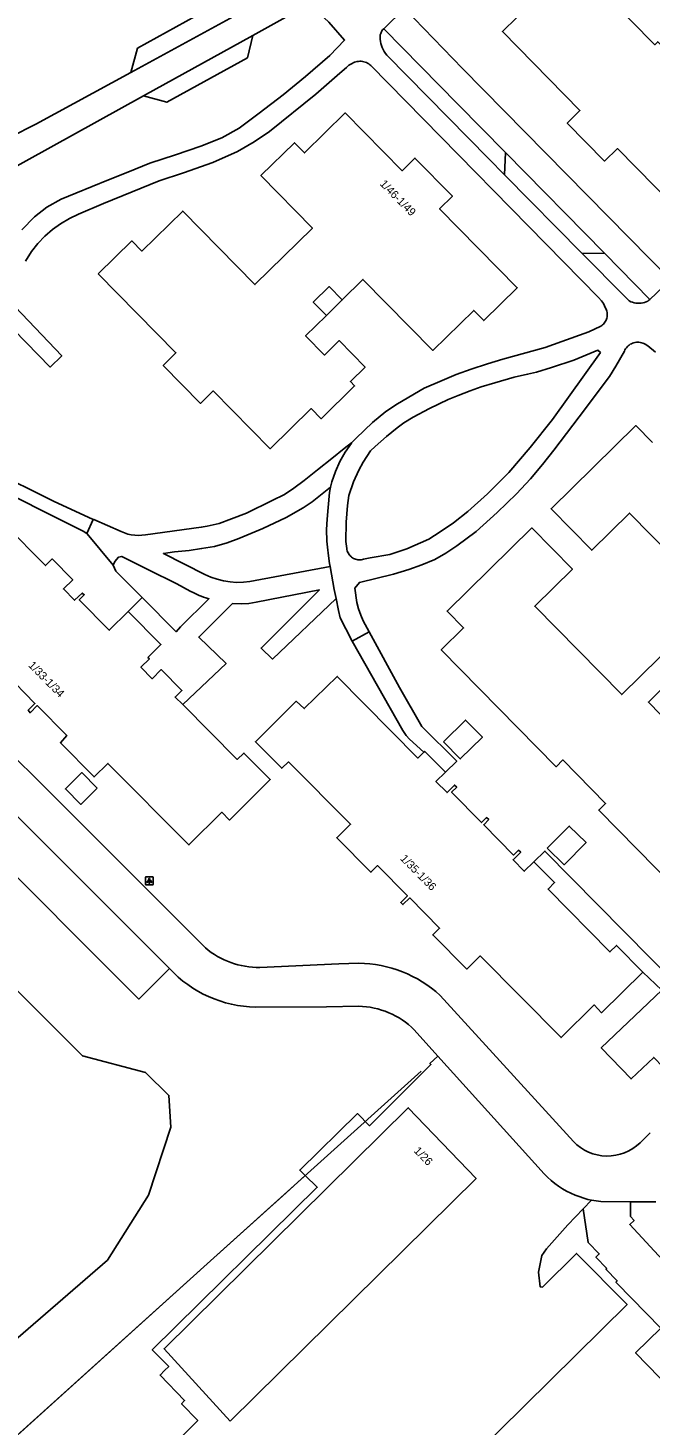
# Model space of a CAD drawing. Extents: x 162791 to 163827, y 385795 to 386523.
# Drawn here: x 162911.4 to 162989.1, y 385940.4 to 386115 of the extents above; entities that cross this region are included whole.
import ezdxf

# ---------------------------------------------------------------- set-up
doc = ezdxf.new("R2010")
doc.units = 0
for name, color, linetype in [('IMGEO_Grasland_overig', 7, 'Continuous'), ('IMGEO_Groenvoorziening', 7, 'Continuous'), ('IMGEO_Hek', 7, 'Continuous'), ('IMGEO_Lichtpunt', 7, 'Continuous'), ('IMGEO_Loofbos', 7, 'Continuous'), ('IMGEO_Pand', 7, 'Continuous'), ('IMGEO_Pand_nummerreeks', 7, 'Continuous'), ('IMGEO_Pand_overbouw', 7, 'Continuous'), ('IMGEO_Parkeervlak_halfverhard', 7, 'Continuous'), ('IMGEO_Parkeervlak_open', 7, 'Continuous'), ('IMGEO_Terreindeel_open', 7, 'Continuous'), ('IMGEO_Voetpad_open', 7, 'Continuous'), ('IMGEO_Woonerf_gesloten', 7, 'Continuous'), ('IMGEO_Woonerf_open', 7, 'Continuous')]:
    doc.layers.add(name, color=color, linetype=linetype)

msp = doc.modelspace()

# ---------------------------------------------------------------- linework, layer by layer
at = {"layer": 'IMGEO_Grasland_overig'}
for points in [[(162946.01, 385971.54), (162947.5, 385970.08), (162926.89, 385949.75), (162928.94, 385947.68), (162928.43, 385947.18), (162927.86, 385946.61), (162930.93, 385943.42), (162930.55, 385943.02), (162932.57, 385940.93), (162894.88, 385903.13), (162917.15, 385880.93), (162957.72, 385920.28), (162954.26, 385923.85), (162986.21, 385955.41), (162979.9, 385961.8), (162975.64, 385957.59), (162975.37, 385957.61), (162975.15, 385959.46), (162975.57, 385961.56), (162976.13, 385962.36), (162978.82, 385965.4), (162980.71, 385967.36)], [(163004.99, 385938.91), (163001.1, 385935.13), (162993.27, 385943.2), (162987.27, 385949.39), (162990.42, 385952.45), (162984.93, 385958.1), (162984.82, 385958.21), (162984.99, 385958.38), (162983.58, 385959.83), (162983.68, 385959.93), (162982.32, 385961.34), (162982.74, 385961.74), (162981.36, 385963.16), (162980.71, 385967.36)]]:
    msp.add_lwpolyline(points, dxfattribs=at)
at = {"layer": 'IMGEO_Groenvoorziening'}
for points in [[(162922, 386047.82), (162922.32, 386047.08), (162925.62, 386043.77)], [(162986.64, 385968.27), (162986.63, 385966.43), (162987.09, 385965.94), (162986.55, 385965.43), (162994.73, 385956.59)]]:
    msp.add_lwpolyline(points, dxfattribs=at)
at = {"layer": 'IMGEO_Hek'}
msp.add_lwpolyline([(162960.5, 385984.6), (162933.35, 385960.12), (162858.79, 385892.9), (162856.26, 385890.62), (162855.6, 385890.02)], dxfattribs=at)
at = {"layer": 'IMGEO_Lichtpunt'}
for p, q in [((162926.03, 386008.78), (162926.03, 386007.97)), ((162926.03, 386008.78), (162926.03, 386007.97)), ((162926.93, 386008.87), (162926.12, 386008.87)), ((162926.93, 386008.87), (162926.12, 386008.87)), ((162927.02, 386007.97), (162927.02, 386008.78)), ((162927.02, 386007.97), (162927.02, 386008.78)), ((162926.12, 386007.87), (162926.93, 386007.87)), ((162926.12, 386007.87), (162926.93, 386007.87))]:
    msp.add_line(p, q, dxfattribs=at)
for points in [[(162926.4, 386008.44), (162926.44, 386008.41), (162926.25, 386008.15), (162926.21, 386008.18), (162926.4, 386008.44)], [(162926.5, 386008.39), (162926.55, 386008.39), (162926.55, 386008.07), (162926.5, 386008.07), (162926.5, 386008.39)], [(162926.61, 386008.41), (162926.65, 386008.44), (162926.84, 386008.18), (162926.8, 386008.15), (162926.61, 386008.41)]]:
    msp.add_lwpolyline(points, dxfattribs=at)
msp.add_circle((162926.53, 386008.57), 0.0994, dxfattribs=at)
for centre, start, end in [((162926.12, 386008.78), 90, 180), ((162926.12, 386008.78), 90, 180), ((162926.93, 386008.78), 0, 90), ((162926.93, 386008.78), 0, 90), ((162926.12, 386007.97), 180, 270), ((162926.12, 386007.97), 180, 270), ((162926.93, 386007.97), 270, 0), ((162926.93, 386007.97), 270, 360)]:
    msp.add_arc(centre, 0.0946, start, end, dxfattribs=at)
at = {"layer": 'IMGEO_Loofbos'}
for points in [[(162897.24, 385952.74), (162896.83, 385956.99), (162891.77, 385960.95), (162855.62, 385982.78), (162871.57, 386018.63), (162879.63, 386025.07), (162918.16, 385986.52), (162926.05, 385984.41), (162928.96, 385981.55), (162929.2, 385977.6), (162926.4, 385969.1), (162921.28, 385960.95), (162900.79, 385943.25), (162895.78, 385949.48), (162897.24, 385952.74)], [(162946.01, 385971.54), (162945.32, 385972.22), (162952.52, 385979.29), (162954.04, 385977.77), (162961.71, 385985.4), (162961.58, 385985.54), (162962.58, 385986.48)], [(162874.36, 385906.94), (162894.46, 385925.05), (162933.35, 385960.12), (162943.62, 385969.38), (162946.01, 385971.54)]]:
    msp.add_lwpolyline(points, dxfattribs=at)
at = {"layer": 'IMGEO_Pand'}
for points in [[(162980.76, 386121.94), (162989.67, 386112.87), (162990.05, 386113.24), (162990.8, 386112.47), (162992.54, 386114.18), (162991.78, 386114.95), (162995.01, 386118.12)], [(163020.25, 386110.15), (163016.67, 386106.63), (163015.42, 386107.91), (163010.14, 386102.72), (163001.39, 386111.62), (162996.06, 386106.38), (163002.63, 386099.69), (162999.05, 386096.17), (162997.38, 386097.87), (162992.1, 386092.69), (162985.01, 386099.9), (162983.41, 386098.34), (162978.74, 386103.09), (162980.33, 386104.65), (162970.65, 386114.51), (162974.23, 386118.03)], [(162920.15, 386084.24), (162924.34, 386088.35), (162925.59, 386087.08), (162930.69, 386092.09), (162939.72, 386082.9), (162946.91, 386089.96), (162940.47, 386096.52), (162944.66, 386100.63), (162945.91, 386099.35), (162951.01, 386104.36), (162958.12, 386097.13), (162959.71, 386098.7), (162964.39, 386093.95), (162962.79, 386092.38), (162972.49, 386082.51), (162968.31, 386078.39), (162967.05, 386079.67), (162961.96, 386074.66), (162953.22, 386083.54), (162950.62, 386080.98), (162949, 386082.64), (162947.01, 386080.69), (162948.64, 386079.03), (162948.61, 386079.01), (162946.04, 386076.48), (162948.39, 386074.08), (162950.23, 386075.9), (162953.49, 386072.58), (162951.65, 386070.77), (162952.17, 386070.23), (162947.99, 386066.12), (162946.73, 386067.39), (162941.63, 386062.38), (162934.52, 386069.61), (162932.93, 386068.05), (162928.26, 386072.8), (162929.85, 386074.37), (162920.15, 386084.24)], [(162989.38, 386063.17), (162987.31, 386065.27), (162976.73, 386054.87), (162981.81, 386049.7), (162986.52, 386054.33), (162997.38, 386043.28), (162985.55, 386031.65), (162974.69, 386042.7), (162979.39, 386047.32), (162974.31, 386052.49), (162963.73, 386042.09), (162965.79, 386039.99), (162962.99, 386037.24), (162977.34, 386022.64), (162978.2, 386023.49), (162983.54, 386018.05), (162982.68, 386017.21), (162997.02, 386002.61)], [(162923.88, 386042.04), (162921.52, 386039.7), (162917.77, 386043.48), (162918.4, 386044.13), (162918.15, 386044.34), (162917.19, 386043.45), (162915.78, 386044.86), (162916.96, 386046.01), (162914.39, 386048.61), (162913.53, 386047.77), (162903.43, 386057.97), (162899.33, 386053.91), (162898.43, 386054.79)], [(162930.69, 386030.4), (162937.49, 386023.54), (162938.35, 386024.34), (162941.64, 386021.02), (162936.53, 386015.97), (162935.58, 386016.95), (162931.46, 386012.86), (162921.35, 386023.04), (162919.63, 386021.37), (162915.41, 386025.64), (162916.2, 386026.52), (162912.52, 386030.27), (162911.63, 386029.39), (162911.39, 386029.7), (162912.23, 386030.53), (162908.52, 386034.36), (162907.67, 386033.47), (162903.43, 386037.77), (162905.11, 386039.44), (162897.39, 386047.31), (162896.54, 386046.45), (162893.34, 386049.69)], [(162930.69, 386030.4), (162929.75, 386031.34), (162930.59, 386032.17), (162928.02, 386034.78), (162926.88, 386033.64), (162925.48, 386035.07), (162926.53, 386036.11), (162926.34, 386036.3), (162927.97, 386037.92), (162923.88, 386042.04)], [(162991.9, 386027.64), (162988.88, 386030.71), (162993.37, 386035.12), (162996.39, 386032.04), (162991.9, 386027.64)], [(162988.2, 385996.97), (162983.04, 385991.89), (162982.1, 385992.86), (162977.98, 385988.79), (162967.88, 385998.99), (162966.18, 385997.34), (162961.94, 386001.62), (162962.78, 386002.45), (162959.06, 386006.25), (162958.21, 386005.4), (162957.93, 386005.68), (162958.77, 386006.52), (162955.05, 386010.29), (162954.2, 386009.45), (162949.95, 386013.76), (162951.66, 386015.45), (162943.93, 386023.24), (162943.07, 386022.44), (162939.78, 386025.76), (162944.89, 386030.83), (162945.89, 386029.9), (162950, 386033.92), (162960.08, 386023.71), (162960.81, 386024.44)], [(162963.26, 386025.74), (162965.37, 386023.61), (162968.14, 386026.34), (162966.03, 386028.47), (162963.26, 386025.74)], [(162963.51, 386021.95), (162960.93, 386024.56), (162960.81, 386024.44)], [(162920.01, 386019.97), (162917.96, 386017.93), (162916.04, 386019.86), (162918.1, 386021.9), (162920.01, 386019.97)], [(162974.57, 386010.75), (162973.37, 386009.58), (162971.98, 386011.02), (162972.94, 386011.95), (162972.67, 386012.2), (162972.04, 386011.6), (162968.3, 386015.38), (162968.93, 386016.02), (162968.67, 386016.29), (162968.03, 386015.65), (162964.28, 386019.45), (162964.93, 386020.07), (162964.64, 386020.35), (162963.72, 386019.41), (162962.33, 386020.81), (162963.51, 386021.95)], [(162976.25, 386012.45), (162978.35, 386010.38), (162981.09, 386013.15), (162979, 386015.22), (162976.25, 386012.45)], [(162974.57, 386010.75), (162977.15, 386008.15), (162976.34, 386007.34), (162984.08, 385999.49), (162984.9, 386000.3), (162988.2, 385996.97)], [(162994.39, 385991), (162991.77, 385988.59), (162992.99, 385987.33), (162990.67, 385985.11), (162989.54, 385986.3), (162986.71, 385983.61), (162983, 385987.51), (162990.54, 385994.69)], [(162936.63, 385940.85), (162928.36, 385949.9), (162958.88, 385980.01), (162967.35, 385971.15), (162964.37, 385968.21), (162936.63, 385940.85)]]:
    msp.add_lwpolyline(points, dxfattribs=at)
at = {"layer": 'IMGEO_Pand_overbouw'}
msp.add_lwpolyline([(162950.62, 386080.98), (162949, 386082.64), (162947.01, 386080.69), (162948.64, 386079.03)], close=True, dxfattribs=at)
at = {"layer": 'IMGEO_Parkeervlak_halfverhard'}
for points in [[(162929.05, 385997.41), (162925.23, 385993.59), (162884.23, 386034.61), (162888.05, 386038.43)], [(162888.05, 386038.43), (162926.46, 386000), (162929.05, 385997.41)]]:
    msp.add_lwpolyline(points, dxfattribs=at)
at = {"layer": 'IMGEO_Parkeervlak_open'}
for points in [[(162937.97, 386116.9), (162934.71, 386117.77), (162925.05, 386112.43), (162924.21, 386109.41)], [(162924.21, 386109.41), (162937.97, 386116.9)], [(162939.45, 386114.03), (162938.78, 386111.25), (162928.69, 386105.68), (162925.79, 386106.48)], [(162939.45, 386114.03), (162925.79, 386106.48)], [(162971.01, 386099.41), (162970.91, 386096.63)], [(162983.38, 386086.82), (162971.01, 386099.41)], [(162980.62, 386086.79), (162970.91, 386096.63)], [(162980.62, 386086.79), (162983.38, 386086.82)]]:
    msp.add_lwpolyline(points, dxfattribs=at)
at = {"layer": 'IMGEO_Terreindeel_open'}
msp.add_lwpolyline([(162980.71, 385967.36), (162981.77, 385968.48)], dxfattribs=at)
at = {"layer": 'IMGEO_Voetpad_open'}
for points in [[(162908.94, 386080.98), (162915.59, 386073.99), (162914.14, 386072.58), (162908.08, 386078.79)], [(162996.59, 385991.77), (162995.75, 385991.99), (162975.95, 386012.1), (162974.57, 386010.75)], [(162988.2, 385996.97), (162990.54, 385994.69)]]:
    msp.add_lwpolyline(points, dxfattribs=at)
at = {"layer": 'IMGEO_Woonerf_gesloten'}
for points in [[(162946.59, 386117.98), (162946.82, 386117.74), (162947.8, 386116.79), (162948.95, 386115.69), (162950.92, 386113.46), (162949.06, 386111.52), (162946.03, 386108.9), (162943.24, 386106.61), (162940.24, 386104.34), (162937.76, 386102.46), (162935.59, 386101.26), (162932.96, 386100.21), (162929.79, 386099.11), (162926.6, 386098.08), (162923.82, 386096.95), (162921.43, 386095.97), (162917.36, 386094.34), (162915.52, 386093.59), (162913.7, 386092.56), (162912.19, 386091.35), (162910.59, 386089.72)], [(162955.83, 386114.88), (162958.39, 386117.42)], [(162970.91, 386096.63), (162968.96, 386098.61), (162956.21, 386111.59), (162956.03, 386111.8), (162955.87, 386112.02), (162955.74, 386112.26), (162955.62, 386112.51), (162955.52, 386112.76), (162955.45, 386113.02), (162955.39, 386113.29), (162955.36, 386113.56), (162955.36, 386113.83), (162955.37, 386114.1), (162955.43, 386114.28), (162955.58, 386114.62), (162955.67, 386114.72), (162955.83, 386114.88)], [(162951.8, 386063.11), (162952.36, 386063.71), (162954.4, 386065.67), (162956.06, 386067.02), (162957.52, 386068.01), (162960.88, 386069.94), (162963.12, 386070.93), (162964.88, 386071.64), (162966.75, 386072.32), (162968.76, 386072.98), (162970.71, 386073.56), (162975.99, 386075.02), (162978.07, 386075.78), (162981.44, 386076.99), (162982.93, 386077.7), (162983.05, 386077.78), (162983.16, 386077.87), (162983.27, 386077.97), (162983.36, 386078.07), (162983.45, 386078.19), (162983.52, 386078.31), (162983.59, 386078.44), (162983.64, 386078.57), (162983.68, 386078.71), (162983.72, 386078.85), (162983.73, 386078.99), (162983.74, 386079.13), (162983.73, 386079.28), (162983.72, 386079.42), (162983.69, 386079.56), (162983.64, 386079.7), (162983.59, 386079.83), (162983.52, 386079.96), (162983.27, 386080.52), (162983.02, 386080.87), (162982.66, 386081.28), (162954.19, 386110.27), (162954.07, 386110.38), (162953.93, 386110.48), (162953.79, 386110.57), (162953.64, 386110.64), (162953.48, 386110.7), (162953.32, 386110.75), (162953.16, 386110.79), (162952.99, 386110.81), (162952.82, 386110.81), (162952.65, 386110.8), (162952.49, 386110.78), (162952.33, 386110.74), (162952.17, 386110.69), (162952.01, 386110.62), (162951.86, 386110.54), (162951.72, 386110.45), (162951.46, 386110.31), (162951.14, 386110.02), (162950.34, 386109.31), (162947.31, 386106.7), (162941.55, 386102.01), (162939.63, 386100.72), (162937.54, 386099.54), (162934.44, 386098.16), (162930.78, 386096.85), (162927.75, 386095.85), (162924.39, 386094.51), (162920.81, 386093.02), (162917.68, 386091.68), (162916.53, 386091.14), (162915.44, 386090.5), (162914.41, 386089.77), (162913.45, 386088.93), (162912.58, 386088.02), (162911.79, 386087.03), (162911.06, 386085.83)], [(162989.08, 386081.02), (162988.94, 386080.93), (162988.82, 386080.84), (162988.62, 386080.75), (162988.41, 386080.67), (162988.19, 386080.61), (162987.97, 386080.58), (162987.75, 386080.56), (162987.53, 386080.56), (162987.31, 386080.58), (162987.09, 386080.62), (162986.88, 386080.68), (162986.67, 386080.75), (162986.47, 386080.85), (162985.93, 386081.41), (162980.62, 386086.79)], [(162991.63, 386083.51), (162989.08, 386081.02)], [(162908.08, 386078.79), (162907.74, 386077.85), (162905.4, 386071.21), (162904.45, 386069.03), (162903.59, 386067.18), (162902.43, 386064.8), (162901.3, 386062.23), (162899.51, 386058.14), (162902.88, 386061.5), (162906.64, 386059.76), (162914.56, 386055.81), (162919.49, 386053.55)], [(162954, 386039.5), (162953.26, 386040.86), (162952.93, 386041.59), (162952.65, 386042.36), (162952.43, 386043.16), (162952.2, 386044.97), (162952.77, 386045.68), (162957.05, 386046.72), (162958.93, 386047.28), (162960.58, 386047.87), (162962.18, 386048.54), (162963.56, 386049.32), (162964.95, 386050.23), (162967.35, 386052.02), (162969.99, 386054.4), (162972.4, 386056.76), (162974.15, 386058.62), (162975.63, 386060.42), (162977.08, 386062.21), (162980.23, 386066.36), (162984.02, 386071.4), (162984.83, 386072.72), (162985.88, 386074.59), (162985.95, 386074.74), (162986.04, 386074.88), (162986.13, 386075.01), (162986.24, 386075.13), (162986.36, 386075.24), (162986.48, 386075.34), (162986.62, 386075.43), (162986.76, 386075.5), (162986.91, 386075.57), (162987.06, 386075.62), (162987.22, 386075.66), (162987.38, 386075.68), (162987.54, 386075.69), (162987.7, 386075.68), (162987.86, 386075.66), (162988.02, 386075.63), (162988.18, 386075.58), (162988.33, 386075.52), (162988.47, 386075.45), (162988.81, 386075.23), (162989.77, 386074.46)], [(162971.45, 386059.4), (162968.76, 386056.74), (162966.3, 386054.54), (162964.53, 386053.14), (162962.87, 386051.98), (162961.43, 386051.08), (162958.69, 386049.85), (162956.56, 386049.16), (162954.12, 386048.73), (162953.28, 386048.56), (162953.14, 386048.52), (162953, 386048.49), (162952.86, 386048.48), (162952.72, 386048.48), (162952.58, 386048.49), (162952.44, 386048.52), (162952.3, 386048.56), (162952.17, 386048.61), (162952.04, 386048.67), (162951.92, 386048.74), (162951.8, 386048.82), (162951.69, 386048.91), (162951.6, 386049.02), (162951.51, 386049.13), (162951.43, 386049.24), (162951.36, 386049.37), (162951.3, 386049.5), (162951.26, 386049.63), (162951.22, 386049.77), (162951.2, 386049.91), (162951.07, 386050.8), (162951.13, 386053.19), (162951.28, 386055.29), (162951.44, 386056.54), (162952.05, 386058.23), (162952.68, 386059.72), (162953.24, 386060.71), (162954.15, 386062.1), (162954.76, 386062.65), (162956.14, 386063.9), (162957.5, 386064.99), (162958.34, 386065.6), (162959.5, 386066.31), (162961.53, 386067.43), (162963.86, 386068.54), (162965.12, 386069.04), (162966.6, 386069.62), (162968, 386070.11), (162969.69, 386070.62), (162972.11, 386071.34), (162973.78, 386071.7), (162974.9, 386071.97), (162976.78, 386072.55), (162979.56, 386073.46), (162981.55, 386074.27), (162982.56, 386074.69), (162982.88, 386074.4), (162976.88, 386066.03), (162974.12, 386062.52), (162971.45, 386059.4)], [(162951.8, 386063.11), (162951.77, 386063.07), (162951, 386061.96), (162950.33, 386060.77), (162949.78, 386059.53), (162949.34, 386058.24), (162949.18, 386057.59)], [(162898.43, 386054.79), (162903.18, 386059.54), (162908.08, 386057.22), (162913.09, 386054.65), (162918.26, 386052.07), (162918.7, 386051.78)], [(162949.18, 386057.59), (162949.03, 386056.92), (162948.85, 386055.03), (162948.76, 386053.58), (162948.67, 386052.3), (162948.72, 386050.83), (162948.8, 386050.06), (162948.89, 386048.98), (162949.03, 386048.05), (162949.1, 386047.65)], [(162918.7, 386051.78), (162919.49, 386053.55)], [(162949.1, 386047.65), (162949.63, 386044.8), (162949.85, 386043.68)], [(162888.58, 386044.93), (162933.53, 386000)], [(162951.88, 386038.31), (162951.07, 386039.89), (162950.36, 386041.23), (162950.14, 386042.15), (162949.85, 386043.68)], [(162951.88, 386038.31), (162954, 386039.5)], [(162940.34, 385997.54), (162950.21, 385998), (162952.69, 385998.07)], [(162962.87, 385994.06), (162979.52, 385975.79)], [(162952.69, 385992.7), (162948.68, 385992.61), (162939.8, 385992.6)], [(162962.58, 385986.48), (162959.63, 385989.75)], [(162975.87, 385971.76), (162962.58, 385986.48)], [(162987.84, 385975.64), (162989.09, 385976.86)], [(162981.77, 385968.48), (162981.3, 385968.56), (162979.74, 385969.09)], [(162981.77, 385968.48), (162982.93, 385968.29), (162986.64, 385968.27)], [(162986.64, 385968.27), (162989.82, 385968.26)]]:
    msp.add_lwpolyline(points, dxfattribs=at)
for centre, radius, start, end in [((162940.25, 386007.94), 10.4, 229.7452, 270.482), ((162940.09, 386007.67), 15.08, 222.9134, 268.8929), ((162952.51, 385982.69), 15.38, 47.6678, 89.3535), ((162952.49, 385982.59), 10.11, 45.1056, 88.8826), ((162983.75, 385979.82), 5.84, 223.5423, 314.3637), ((162983.83, 385979.16), 10.88, 222.9008, 247.8814)]:
    msp.add_arc(centre, radius, start, end, dxfattribs=at)
at = {"layer": 'IMGEO_Woonerf_open'}
for points in [[(162946.59, 386117.98), (162939.45, 386114.03)], [(162958.39, 386117.42), (162965.64, 386109.89), (162991.63, 386083.51)], [(162955.83, 386114.88), (162965.08, 386105.45), (162971.01, 386099.41)], [(162924.21, 386109.41), (162912.34, 386102.94), (162906.04, 386099.77), (162899.07, 386092.64), (162895.33, 386089.16), (162877.37, 386060.3), (162874.79, 386059.32)], [(162925.79, 386106.48), (162908.42, 386096.88), (162904.91, 386093.86), (162896.91, 386085.21), (162889.98, 386073.46), (162879.93, 386057.68), (162878.87, 386053.05)], [(162983.38, 386086.82), (162989.08, 386081.02)], [(162919.49, 386053.55), (162919.57, 386053.52), (162923, 386052.02), (162923.41, 386051.85), (162923.83, 386051.71), (162924.27, 386051.62), (162924.71, 386051.56), (162925.15, 386051.54), (162925.6, 386051.56), (162926.04, 386051.62), (162933.01, 386052.57), (162933.74, 386052.7), (162935.25, 386053.05), (162936.8, 386053.62), (162938.66, 386054.33), (162941.89, 386055.9), (162943.4, 386056.65), (162944.58, 386057.44), (162945.88, 386058.39), (162947.55, 386059.73), (162949.33, 386061.18), (162950.86, 386062.42), (162951.8, 386063.11)], [(162949.18, 386057.59), (162946.88, 386055.76), (162945.74, 386054.98), (162943.62, 386053.77), (162940.69, 386052.43), (162937.72, 386051.16), (162936.23, 386050.64), (162934.66, 386050.18), (162933.05, 386049.9), (162931.51, 386049.65), (162929.66, 386049.48), (162928.28, 386049.3), (162933.44, 386046.66), (162934.19, 386046.33), (162934.98, 386046.06), (162935.79, 386045.86), (162936.61, 386045.73), (162937.43, 386045.68), (162938.27, 386045.71), (162939.09, 386045.8), (162949.1, 386047.65)], [(162922, 386047.82), (162918.76, 386051.74), (162918.7, 386051.78)], [(162925.62, 386043.77), (162929.86, 386039.51), (162930.43, 386040.12), (162933.97, 386043.63), (162933.59, 386043.74), (162933.3, 386043.83), (162933.02, 386043.94), (162932.74, 386044.05), (162932.1, 386044.35), (162931.63, 386044.59), (162929.94, 386045.49), (162926.41, 386047.23), (162923.07, 386048.93), (162922.67, 386048.81), (162922.21, 386048.3), (162922, 386047.82)], [(162923.88, 386042.04), (162925.62, 386043.77)], [(162949.85, 386043.68), (162941.91, 386036.08), (162940.49, 386037.46), (162947.78, 386044.73), (162939.86, 386043.21), (162938.95, 386043.05), (162938.01, 386042.99), (162936.92, 386043.05), (162932.69, 386038.83), (162936.11, 386035.52), (162930.69, 386030.4)], [(162963.51, 386021.95), (162964.93, 386023.35), (162960.59, 386027.67), (162957.79, 386032.55), (162954, 386039.5)], [(162960.81, 386024.44), (162959.02, 386026.09), (162958.63, 386026.54), (162958.2, 386027.18), (162951.88, 386038.31)]]:
    msp.add_lwpolyline(points, dxfattribs=at)

# ---------------------------------------------------------------- texts
at = {"layer": 'IMGEO_Pand_nummerreeks'}
for s, rotation, p in [('1/46-1/49', 314.4556, (162955.26, 386095.41)), ('1/33-1/34', 314.5587, (162911.33, 386035.24)), ('1/35-1/36', 314.6962, (162957.8, 386011.08)), ('1/26', 314.3544, (162959.5, 385974.56))]:
    msp.add_text(s, height=1, rotation=rotation, dxfattribs=at).set_placement(p)

doc.saveas('drawing.dxf')
